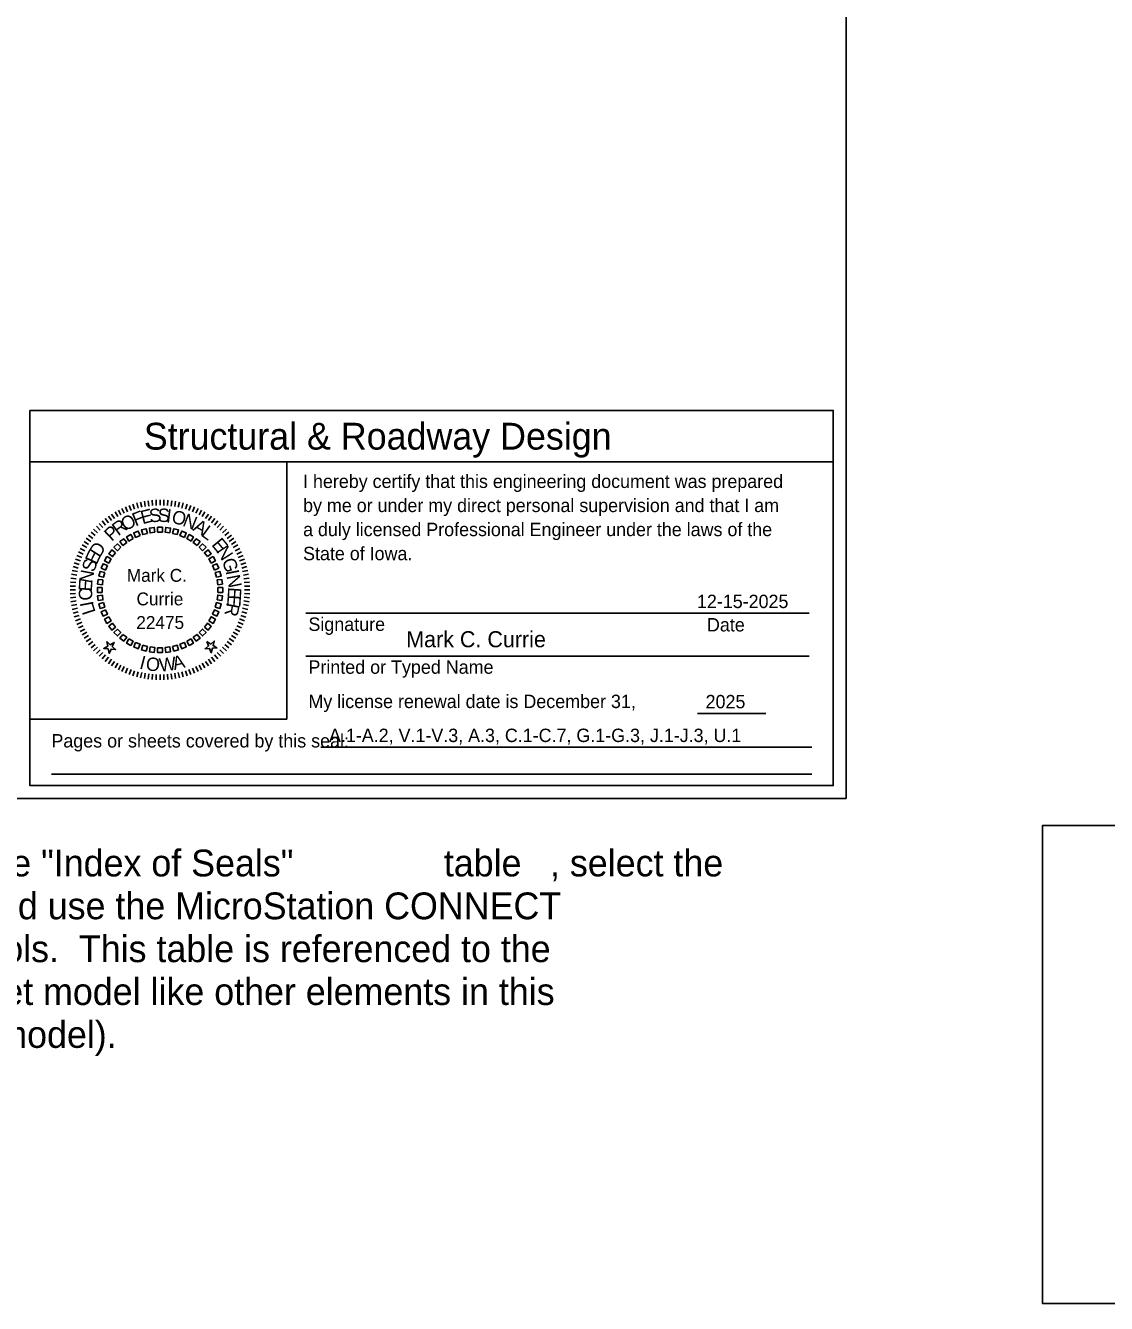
# Model space of a CAD drawing. Extents: x -0.84 to 4.97, y -1.01 to 2.42.
# Drawn here: x 2.085 to 2.925, y -0.289 to 0.704 of the extents above; entities that cross this region are included whole.
import ezdxf

# ---------------------------------------------------------------- set-up
doc = ezdxf.new("R2010")
doc.units = 0
for name, color, linetype in [('Level 1', 7, 'Continuous'), ('Level 2', 7, 'Continuous'), ('OBD_Construction_Line', 7, 'Continuous'), ('SheetGridMajor', 7, 'Continuous'), ('SheetGridMinor', 7, 'Continuous'), ('SheetText', 7, 'Continuous'), ('TextNonPlot', 7, 'Continuous')]:
    doc.layers.add(name, color=color, linetype=linetype)

msp = doc.modelspace()

# ---------------------------------------------------------------- linework, layer by layer
at = {"layer": 'Level 1'}
for p, q in [((2.16132, 0.32512), (2.15956, 0.3289)), ((2.16395, 0.32628), (2.16236, 0.33013)), ((2.16663, 0.32732), (2.1652, 0.33123)), ((2.16935, 0.32824), (2.16809, 0.33221)), ((2.1721, 0.32904), (2.17103, 0.33307)), ((2.17489, 0.32973), (2.17399, 0.3338)), ((2.17771, 0.33029), (2.17699, 0.33439)), ((2.18055, 0.33072), (2.18001, 0.33486)), ((2.18341, 0.33104), (2.18304, 0.33519)), ((2.18627, 0.33123), (2.18609, 0.33539)), ((2.18914, 0.33129), (2.18914, 0.33545)), ((2.19202, 0.33122), (2.1922, 0.33539)), ((2.19488, 0.33104), (2.19524, 0.33519)), ((2.19774, 0.33072), (2.19828, 0.33486)), ((2.20058, 0.33029), (2.2013, 0.33439)), ((2.20339, 0.32973), (2.20429, 0.33379)), ((2.20618, 0.32904), (2.20726, 0.33307)), ((2.20894, 0.32824), (2.21019, 0.33221)), ((2.21166, 0.32732), (2.21308, 0.33123)), ((2.21434, 0.32628), (2.21593, 0.33013)), ((2.21697, 0.32512), (2.21873, 0.3289)), ((2.14683, 0.31589), (2.14415, 0.31908)), ((2.14907, 0.31768), (2.14653, 0.32099)), ((2.15138, 0.31938), (2.14899, 0.3228)), ((2.15377, 0.32098), (2.15153, 0.32449)), ((2.15623, 0.32247), (2.15414, 0.32608)), ((2.15875, 0.32385), (2.15682, 0.32755)), ((2.21954, 0.32385), (2.22147, 0.32754)), ((2.22206, 0.32247), (2.22414, 0.32608)), ((2.22452, 0.32098), (2.22675, 0.32449)), ((2.2269, 0.31938), (2.22929, 0.32279)), ((2.22922, 0.31768), (2.23176, 0.32099)), ((2.23146, 0.31589), (2.23414, 0.31908)), ((2.13691, 0.30553), (2.13361, 0.30807)), ((2.13871, 0.30777), (2.13552, 0.31045)), ((2.14061, 0.30993), (2.13753, 0.31275)), ((2.14259, 0.31201), (2.13965, 0.31495)), ((2.14467, 0.31399), (2.14185, 0.31706)), ((2.23362, 0.31399), (2.23643, 0.31706)), ((2.23569, 0.31201), (2.23864, 0.31495)), ((2.23768, 0.30993), (2.24075, 0.31274)), ((2.23957, 0.30777), (2.24277, 0.31045)), ((2.24137, 0.30553), (2.24468, 0.30807)), ((2.13213, 0.29837), (2.12852, 0.30045)), ((2.13362, 0.30083), (2.13011, 0.30307)), ((2.13522, 0.30322), (2.1318, 0.3056)), ((2.24307, 0.30321), (2.24648, 0.3056)), ((2.24467, 0.30083), (2.24818, 0.30306)), ((2.24616, 0.29837), (2.24976, 0.30045)), ((2.12728, 0.28797), (2.12337, 0.2894)), ((2.12832, 0.29065), (2.12447, 0.29224)), ((2.12948, 0.29328), (2.1257, 0.29504)), ((2.13075, 0.29585), (2.12705, 0.29778)), ((2.24754, 0.29585), (2.25123, 0.29778)), ((2.24881, 0.29328), (2.25258, 0.29504)), ((2.24996, 0.29065), (2.25381, 0.29224)), ((2.25101, 0.28797), (2.25492, 0.2894)), ((2.12487, 0.2797), (2.1208, 0.28061)), ((2.12555, 0.28249), (2.12153, 0.28357)), ((2.12636, 0.28525), (2.12238, 0.2865)), ((2.25193, 0.28525), (2.2559, 0.2865)), ((2.25273, 0.28249), (2.25676, 0.28357)), ((2.25342, 0.2797), (2.25748, 0.2806)), ((2.12337, 0.26833), (2.11921, 0.26851)), ((2.12356, 0.27119), (2.11941, 0.27156)), ((2.12387, 0.27405), (2.11974, 0.27459)), ((2.12431, 0.27689), (2.12021, 0.27761)), ((2.25398, 0.27689), (2.25808, 0.27761)), ((2.25441, 0.27405), (2.25854, 0.27459)), ((2.25473, 0.27119), (2.25888, 0.27156)), ((2.25491, 0.26833), (2.25908, 0.26851)), ((2.12331, 0.26546), (2.11914, 0.26546)), ((2.12337, 0.26258), (2.11921, 0.2624)), ((2.12356, 0.25972), (2.11941, 0.25935)), ((2.25473, 0.25972), (2.25888, 0.25935)), ((2.25491, 0.26258), (2.25908, 0.2624)), ((2.25498, 0.26545), (2.25914, 0.26545)), ((2.12387, 0.25686), (2.11974, 0.25632)), ((2.12431, 0.25402), (2.12021, 0.2533)), ((2.12487, 0.25121), (2.1208, 0.2503)), ((2.25341, 0.25121), (2.25748, 0.2503)), ((2.25398, 0.25402), (2.25808, 0.2533)), ((2.25441, 0.25686), (2.25854, 0.25632)), ((2.12555, 0.24842), (2.12153, 0.24734)), ((2.12636, 0.24566), (2.12238, 0.24441)), ((2.12728, 0.24294), (2.12336, 0.24151)), ((2.12832, 0.24026), (2.12447, 0.23867)), ((2.24996, 0.24026), (2.25381, 0.23867)), ((2.25101, 0.24294), (2.25492, 0.24151)), ((2.25193, 0.24566), (2.2559, 0.2444)), ((2.25273, 0.24842), (2.25676, 0.24734)), ((2.12948, 0.23763), (2.1257, 0.23587)), ((2.13075, 0.23506), (2.12705, 0.23313)), ((2.13213, 0.23254), (2.12852, 0.23046)), ((2.13362, 0.23008), (2.13011, 0.22784)), ((2.24467, 0.23008), (2.24818, 0.22784)), ((2.24616, 0.23254), (2.24976, 0.23045)), ((2.24754, 0.23506), (2.25123, 0.23313)), ((2.24881, 0.23763), (2.25258, 0.23587)), ((2.13522, 0.22769), (2.1318, 0.22531)), ((2.13691, 0.22538), (2.13361, 0.22284)), ((2.13871, 0.22314), (2.13552, 0.22046)), ((2.14061, 0.22098), (2.13753, 0.21816)), ((2.14259, 0.2189), (2.13965, 0.21596)), ((2.23569, 0.2189), (2.23864, 0.21596)), ((2.23768, 0.22098), (2.24075, 0.21816)), ((2.23957, 0.22314), (2.24277, 0.22046)), ((2.24137, 0.22538), (2.24468, 0.22284)), ((2.24307, 0.22769), (2.24648, 0.2253)), ((2.14467, 0.21692), (2.14185, 0.21385)), ((2.14683, 0.21502), (2.14415, 0.21183)), ((2.14907, 0.21323), (2.14653, 0.20992)), ((2.15138, 0.21153), (2.14899, 0.20811)), ((2.15377, 0.20993), (2.15153, 0.20642)), ((2.22451, 0.20993), (2.22675, 0.20642)), ((2.2269, 0.21153), (2.22929, 0.20811)), ((2.22922, 0.21323), (2.23176, 0.20992)), ((2.23146, 0.21502), (2.23414, 0.21183)), ((2.23362, 0.21692), (2.23643, 0.21384)), ((2.15623, 0.20844), (2.15414, 0.20483)), ((2.15874, 0.20706), (2.15682, 0.20336)), ((2.16132, 0.20579), (2.15956, 0.20201)), ((2.16395, 0.20463), (2.16235, 0.20078)), ((2.16663, 0.20359), (2.1652, 0.19968)), ((2.16935, 0.20267), (2.16809, 0.1987)), ((2.1721, 0.20187), (2.17103, 0.19784)), ((2.17489, 0.20118), (2.17399, 0.19711)), ((2.17771, 0.20062), (2.17699, 0.19652)), ((2.18055, 0.20019), (2.18001, 0.19605)), ((2.1834, 0.19987), (2.18304, 0.19572)), ((2.18627, 0.19968), (2.18609, 0.19552)), ((2.18914, 0.19962), (2.18914, 0.19545)), ((2.19201, 0.19968), (2.1922, 0.19552)), ((2.19488, 0.19987), (2.19524, 0.19572)), ((2.19774, 0.20018), (2.19828, 0.19605)), ((2.20057, 0.20062), (2.2013, 0.19652)), ((2.20339, 0.20118), (2.20429, 0.19711)), ((2.20618, 0.20187), (2.20726, 0.19784)), ((2.20894, 0.20267), (2.21019, 0.19869)), ((2.21166, 0.20359), (2.21308, 0.19968)), ((2.21434, 0.20463), (2.21593, 0.20078)), ((2.21696, 0.20579), (2.21873, 0.20201)), ((2.21954, 0.20706), (2.22146, 0.20336)), ((2.22206, 0.20844), (2.22414, 0.20483))]:
    msp.add_line(p, q, dxfattribs=at)
for points in [[(2.16827, 0.30536), (2.16502, 0.30349), (2.16314, 0.30674), (2.16639, 0.30861)], [(2.17365, 0.30775), (2.17019, 0.30631), (2.16875, 0.30978), (2.17222, 0.31121)], [(2.17931, 0.30941), (2.17569, 0.30844), (2.17471, 0.31206), (2.17834, 0.31303)], [(2.18513, 0.31031), (2.18141, 0.30982), (2.18092, 0.31354), (2.18464, 0.31403)], [(2.19102, 0.31045), (2.18727, 0.31045), (2.18727, 0.3142), (2.19102, 0.3142)], [(2.19688, 0.30983), (2.19316, 0.31031), (2.19365, 0.31403), (2.19736, 0.31354)], [(2.2026, 0.30844), (2.19898, 0.30941), (2.19995, 0.31303), (2.20357, 0.31206)], [(2.2081, 0.30631), (2.20463, 0.30775), (2.20607, 0.31121), (2.20953, 0.30978)], [(2.21327, 0.30349), (2.21002, 0.30536), (2.21189, 0.30861), (2.21514, 0.30674)], [(2.15865, 0.2986), (2.156, 0.29595), (2.15335, 0.2986), (2.156, 0.30125)], [(2.16324, 0.3023), (2.16026, 0.30001), (2.15798, 0.30299), (2.16095, 0.30527)], [(2.21802, 0.30001), (2.21505, 0.3023), (2.21733, 0.30527), (2.22031, 0.30299)], [(2.22229, 0.29595), (2.21964, 0.2986), (2.22229, 0.30125), (2.22494, 0.2986)], [(2.15111, 0.28958), (2.14923, 0.28633), (2.14599, 0.28821), (2.14786, 0.29145)], [(2.15458, 0.29434), (2.1523, 0.29136), (2.14933, 0.29364), (2.15161, 0.29662)], [(2.22599, 0.29136), (2.2237, 0.29434), (2.22668, 0.29662), (2.22896, 0.29364)], [(2.22905, 0.28633), (2.22718, 0.28958), (2.23042, 0.29145), (2.2323, 0.28821)], [(2.14616, 0.27891), (2.14519, 0.27529), (2.14157, 0.27626), (2.14254, 0.27988)], [(2.14829, 0.28441), (2.14685, 0.28094), (2.14339, 0.28238), (2.14482, 0.28584)], [(2.23144, 0.28094), (2.23, 0.28441), (2.23346, 0.28584), (2.2349, 0.28238)], [(2.2331, 0.27529), (2.23212, 0.27891), (2.23575, 0.27988), (2.23672, 0.27626)], [(2.14477, 0.27319), (2.14428, 0.26947), (2.14056, 0.26996), (2.14106, 0.27368)], [(2.234, 0.26947), (2.23351, 0.27319), (2.23723, 0.27368), (2.23772, 0.26996)], [(2.14414, 0.26733), (2.14414, 0.26358), (2.14039, 0.26358), (2.14039, 0.26733)], [(2.14428, 0.26144), (2.14477, 0.25772), (2.14105, 0.25723), (2.14057, 0.26095)], [(2.23351, 0.25772), (2.234, 0.26144), (2.23772, 0.26095), (2.23723, 0.25723)], [(2.23414, 0.26358), (2.23414, 0.26733), (2.23789, 0.26733), (2.23789, 0.26358)], [(2.14519, 0.25562), (2.14616, 0.252), (2.14254, 0.25103), (2.14157, 0.25465)], [(2.14685, 0.24997), (2.14829, 0.2465), (2.14482, 0.24507), (2.14339, 0.24853)], [(2.23, 0.2465), (2.23143, 0.24997), (2.2349, 0.24853), (2.23346, 0.24507)], [(2.23212, 0.252), (2.23309, 0.25562), (2.23672, 0.25465), (2.23575, 0.25103)], [(2.14923, 0.24458), (2.15111, 0.24133), (2.14786, 0.23946), (2.14599, 0.2427)], [(2.1523, 0.23955), (2.15458, 0.23657), (2.15161, 0.23429), (2.14933, 0.23726)], [(2.2237, 0.23657), (2.22599, 0.23955), (2.22896, 0.23726), (2.22668, 0.23429)], [(2.22718, 0.24133), (2.22905, 0.24458), (2.2323, 0.2427), (2.23042, 0.23946)], [(2.156, 0.23496), (2.15865, 0.23231), (2.156, 0.22966), (2.15335, 0.23231)], [(2.16026, 0.23089), (2.16324, 0.22861), (2.16095, 0.22564), (2.15798, 0.22792)], [(2.21505, 0.22861), (2.21802, 0.2309), (2.22031, 0.22792), (2.21733, 0.22564)], [(2.21964, 0.23231), (2.22229, 0.23496), (2.22494, 0.23231), (2.22229, 0.22966)], [(2.14771, 0.22523), (2.15034, 0.22285), (2.15341, 0.22463), (2.15197, 0.22139), (2.15461, 0.21902), (2.15108, 0.21939), (2.14964, 0.21615), (2.1489, 0.21962), (2.14538, 0.21999), (2.14845, 0.22176)], [(2.16502, 0.22742), (2.16827, 0.22555), (2.16639, 0.2223), (2.16314, 0.22417)], [(2.17019, 0.2246), (2.17366, 0.22316), (2.17222, 0.2197), (2.16876, 0.22113)], [(2.17569, 0.22247), (2.17931, 0.2215), (2.17834, 0.21788), (2.17471, 0.21885)], [(2.18141, 0.22108), (2.18513, 0.2206), (2.18464, 0.21688), (2.18092, 0.21737)], [(2.18727, 0.22045), (2.19102, 0.22045), (2.19102, 0.2167), (2.18727, 0.2167)], [(2.19316, 0.22059), (2.19688, 0.22108), (2.19737, 0.21737), (2.19365, 0.21688)], [(2.19898, 0.2215), (2.2026, 0.22247), (2.20357, 0.21885), (2.19995, 0.21788)], [(2.20463, 0.22316), (2.2081, 0.2246), (2.20953, 0.22113), (2.20607, 0.2197)], [(2.21002, 0.22555), (2.21327, 0.22742), (2.21514, 0.22417), (2.21189, 0.2223)], [(2.22556, 0.22524), (2.22857, 0.22336), (2.23128, 0.22564), (2.23042, 0.2222), (2.23343, 0.22032), (2.22989, 0.22008), (2.22904, 0.21664), (2.22771, 0.21993), (2.22417, 0.21968), (2.22689, 0.22196)]]:
    msp.add_lwpolyline(points, close=True, dxfattribs=at)
at = {"layer": 'OBD_Construction_Line'}
msp.add_lwpolyline([(0.11042, 1.78667), (2.72292, 1.78667), (2.72292, 0.10333), (0.11042, 0.10333)], close=True, dxfattribs=at)
at = {"layer": 'SheetGridMajor'}
for p, q in [((2.08792, 0.365), (2.71292, 0.365)), ((2.28792, 0.165), (2.28792, 0.365)), ((2.08792, 0.165), (2.28792, 0.165))]:
    msp.add_line(p, q, dxfattribs=at)
msp.add_lwpolyline([(2.08792, 0.405), (2.71292, 0.405), (2.71292, 0.11333), (2.08792, 0.11333)], close=True, dxfattribs=at)
at = {"layer": 'SheetGridMinor'}
for p, q in [((2.69426, 0.24731), (2.3026, 0.24731)), ((2.69426, 0.21398), (2.3026, 0.21398)), ((2.66038, 0.16937), (2.6072, 0.16937)), ((2.31424, 0.14314), (2.69626, 0.14314)), ((2.31424, 0.14314), (2.69626, 0.14314)), ((2.10464, 0.12231), (2.69626, 0.12231))]:
    msp.add_line(p, q, dxfattribs=at)
at = {"layer": 'TextNonPlot'}
for points in [[(2.08792, 0.405), (2.71292, 0.405), (2.71292, 0.11333), (2.08792, 0.11333)], [(4.263, -0.28939), (2.87556, -0.28939), (2.87556, 0.08223), (4.263, 0.08223)]]:
    msp.add_lwpolyline(points, close=True, dxfattribs=at)

# ---------------------------------------------------------------- texts
at = {"layer": 'Level 1'}
for s, rotation, p in [('E', 14.58234, (2.17555, 0.31649)), ('S', 7.39106, (2.1814, 0.3177)), ('S', 0.19978, (2.18748, 0.31826)), ('I', 353.00849, (2.1936, 0.31812)), ('R', 36.1562, (2.15662, 0.3071)), ('O', 28.96491, (2.16216, 0.31088)), ('F', 21.77363, (2.17009, 0.31471)), ('O', 345.81721, (2.19754, 0.31781)), ('N', 338.62592, (2.20606, 0.31555)), ('A', 331.43464, (2.21408, 0.31201)), ('P', 43.34748, (2.15166, 0.3027)), ('L', 324.24335, (2.22042, 0.30801)), ('D', 57.73005, (2.14219, 0.29002)), ('E', 309.86078, (2.22874, 0.30043)), ('N', 302.6695, (2.23245, 0.29575)), ('S', 72.11262, (2.13792, 0.27869)), ('E', 64.92134, (2.13976, 0.28453)), ('G', 288.28693, (2.23721, 0.28831)), ('N', 79.30391, (2.13627, 0.27007)), ('I', 281.09564, (2.24009, 0.2801)), ('E', 86.49519, (2.13615, 0.26407)), ('N', 281.09564, (2.24085, 0.27624)), ('C', 93.68648, (2.13673, 0.2575)), ('E', 266.27731, (2.24183, 0.26179)), ('E', 266.27731, (2.24222, 0.26776)), ('I', 100.87776, (2.13763, 0.25365)), ('L', 108.06904, (2.13921, 0.24824)), ('R', 259.08602, (2.24108, 0.25586)), ('I', 345.29061, (2.17258, 0.20443)), ('O', 352.48189, (2.17767, 0.20319)), ('W', 6.86446, (2.18908, 0.20176)), ('A', 14.05574, (2.20026, 0.20306))]:
    msp.add_text(s, height=0.01042, rotation=rotation, dxfattribs=at).set_placement(p)
at = {"layer": 'Level 2'}
for s, p in [('Mark C.', (2.16331, 0.27179)), ('Currie', (2.17088, 0.25346)), ('22475', (2.1707, 0.23512))]:
    msp.add_text(s, height=0.01, dxfattribs=at).set_placement(p)
at = {"layer": 'SheetText'}
for s, height, p in [('Structural & Roadway Design', 0.0208333, (2.17655, 0.37458)), ('I hereby certify that this engineering document was prepared', 0.0104, (2.30044, 0.34472)), ('by me or under my direct personal supervision and that I am', 0.0104, (2.30044, 0.326)), ('a duly licensed Professional Engineer under the laws of the', 0.0104, (2.30044, 0.30728)), ('State of Iowa.       ', 0.0104, (2.30044, 0.28856)), ('12-15-2025', 0.0104, (2.60685, 0.25134)), ('Signature', 0.010417, (2.30459, 0.23359)), ('Date', 0.010417, (2.61463, 0.23317)), ('Mark C. Currie', 0.0125, (2.38066, 0.22087)), ('Printed or Typed Name', 0.0104167, (2.30459, 0.20026)), ('My license renewal date is December 31,', 0.0104167, (2.30459, 0.17359)), ('2025', 0.0104, (2.61357, 0.1734)), ('Pages or sheets covered by this seal:', 0.0104167, (2.10464, 0.14293)), ('A.1-A.2, V.1-V.3, A.3, C.1-C.7, G.1-G.3, J.1-J.3, U.1', 0.0104, (2.32061, 0.14717))]:
    msp.add_text(s, height=height, dxfattribs=at).set_placement(p)
at = {"layer": 'TextNonPlot'}
for s, height, p in [('To edit the "Index of Seals" ', 0.0208333, (1.95725, 0.04269)), ('table', 0.020833, (2.40994, 0.04269)), (', select the ', 0.0208333, (2.49254, 0.04269)), (' and use the MicroStation CONNECT ', 0.0208333, (2.03985, 0.00936)), ('Table Tools.  This table is referenced to the ', 0.0208333, (1.95725, -0.02398)), ('Title Sheet model like other elements in this ', 0.0208333, (1.95725, -0.05731)), ('drawing model).', 0.0208333, (1.95725, -0.09064))]:
    msp.add_text(s, height=height, dxfattribs=at).set_placement(p)

doc.saveas('drawing.dxf')
